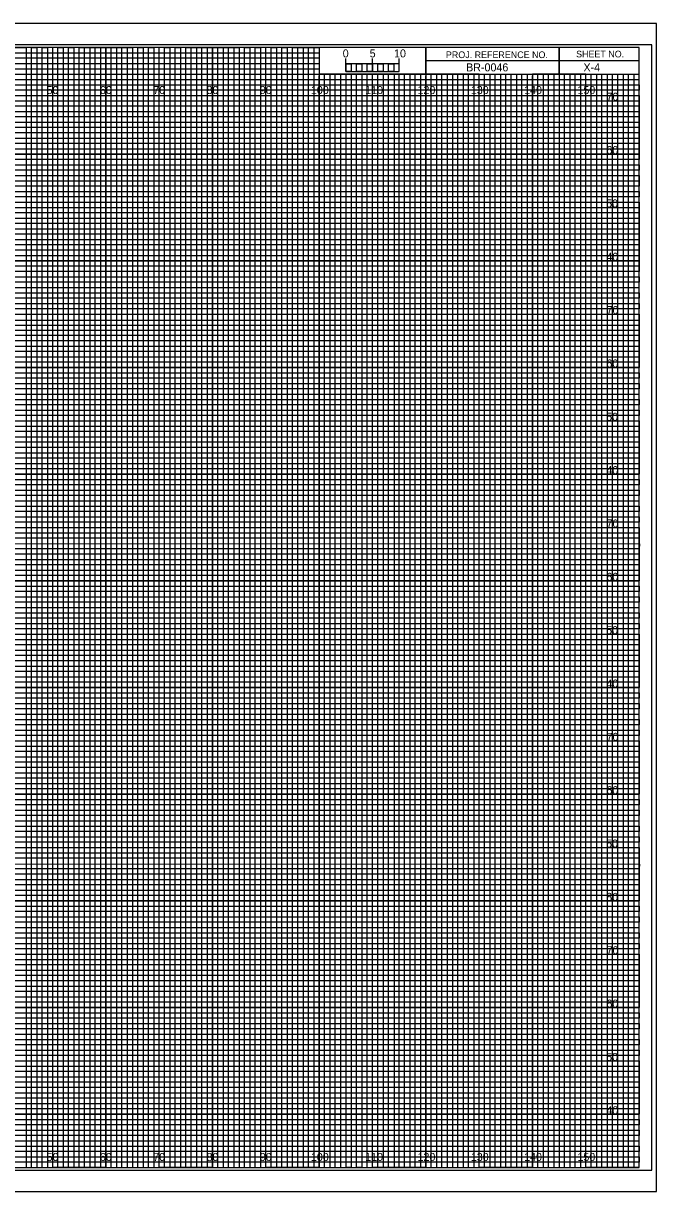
# Model space of a CAD drawing. Extents: x -13 to 323, y 435 to 654.
# Drawn here: x 204.5 to 323.3, y 435.5 to 654.5 of the extents above; entities that cross this region are included whole.
import ezdxf

# ---------------------------------------------------------------- set-up
doc = ezdxf.new("R2010")
doc.units = 0
for name, color, linetype in [('Prop XS Bar Scale Labels', 7, 'Continuous'), ('Prop XS Elevation Labels', 7, 'Continuous'), ('Prop XS Offset Labels', 7, 'Continuous'), ('Prop XS Project Number', 7, 'Continuous'), ('Prop XS Sheet Number', 7, 'Continuous'), ('Sheet Cross Section CELL', 7, 'Continuous'), ('Sheet Cross Section Grid Major CELL', 7, 'Continuous'), ('Sheet Cross Section Grid Middle CELL', 7, 'Continuous'), ('Sheet Cross Section Grid Minor 1 CELL', 7, 'Continuous'), ('Sheet Cross Section Grid Minor 2 CELL', 7, 'Continuous'), ('Sheet Cross Section Scale CELL', 7, 'Continuous'), ('Sheet Cutting Line CELL', 7, 'Continuous'), ('Sheet DOT Grid CELL', 7, 'Continuous'), ('Sheet Plot Border Inside CELL', 7, 'Continuous'), ('Sheet Plot Border Outside CELL', 7, 'Continuous')]:
    doc.layers.add(name, color=color, linetype=linetype)

msp = doc.modelspace()

# ---------------------------------------------------------------- linework, layer by layer
at = {"layer": 'Sheet Cross Section CELL'}
for p, q in [((305, 650), (305, 645)), ((305, 645), (305, 650)), ((280, 647.5), (280, 645)), ((320, 647.49), (280, 647.49)), ((280, 645), (320, 645))]:
    msp.add_line(p, q, dxfattribs=at)
for points in [[(320, 650), (0, 650), (0, 440), (320, 440)], [(280, 650), (260, 650), (260, 645.03), (280, 645.03)], [(320, 650), (280, 650), (280, 645), (320, 645)]]:
    msp.add_lwpolyline(points, close=True, dxfattribs=at)
at = {"layer": 'Sheet Cross Section Grid Major CELL'}
for p, q in [((210, 650), (200, 650)), ((210, 440), (210, 650)), ((230, 650), (220, 650)), ((220, 650), (220, 440)), ((230, 440), (230, 650)), ((250, 650), (240, 650)), ((240, 650), (240, 440)), ((250, 440), (250, 650)), ((260, 650), (260, 440)), ((270, 440), (270, 645)), ((290, 645), (280, 645)), ((280, 645), (280, 440)), ((290, 440), (290, 645)), ((310, 645), (300, 645)), ((300, 645), (300, 440)), ((310, 440), (310, 645)), ((220, 440), (210, 440)), ((240, 440), (230, 440)), ((260, 440), (250, 440)), ((280, 440), (270, 440)), ((300, 440), (290, 440)), ((320, 440), (310, 440)), ((320, 440), (320, 440))]:
    msp.add_line(p, q, dxfattribs=at)
for points in [[(0, 640), (320, 640), (320, 630), (0, 630)], [(0, 620), (320, 620), (320, 610), (0, 610)], [(0, 600), (320, 600), (320, 590), (0, 590)], [(0, 580), (320, 580), (320, 570), (0, 570)], [(0, 560), (320, 560), (320, 550), (0, 550)], [(0, 540), (320, 540), (320, 530), (0, 530)], [(0, 520), (320, 520), (320, 510), (0, 510)], [(0, 500), (320, 500), (320, 490), (0, 490)], [(0, 480), (320, 480), (320, 470), (0, 470)], [(0, 460), (320, 460), (320, 450), (0, 450)]]:
    msp.add_lwpolyline(points, dxfattribs=at)
at = {"layer": 'Sheet Cross Section Grid Middle CELL'}
for points in [[(195, 650), (205, 650), (205, 440), (215, 440), (215, 650), (225, 650), (225, 440), (235, 440), (235, 650), (245, 650), (245, 440), (255, 440), (255, 650), (259.93, 650), (260, 650), (260, 645), (264.99, 645), (264.99, 440), (275, 440), (275, 645), (285, 645), (285, 440), (295, 440), (295, 645), (305, 645), (305, 440), (315, 440), (315, 645)], [(0, 645), (275, 645)], [(0, 625), (320, 625), (320, 635), (0, 635)], [(0, 605), (320, 605), (320, 615), (0, 615)], [(0, 585), (320, 585), (320, 595), (0, 595)], [(0, 565), (320, 565), (320, 575), (0, 575)], [(0, 545), (320, 545), (320, 555), (0, 555)], [(0, 525), (320, 525), (320, 535), (0, 535)], [(0, 505), (320, 505), (320, 515), (0, 515)], [(0, 485), (320, 485), (320, 495), (0, 495)], [(0, 465), (320, 465), (320, 475), (0, 475)], [(0, 445), (320, 445), (320, 455), (0, 455)]]:
    msp.add_lwpolyline(points, dxfattribs=at)
at = {"layer": 'Sheet Cross Section Grid Minor 1 CELL'}
for p, q in [((0, 649), (260, 649)), ((260, 649), (260, 647.98)), ((260, 647.98), (0, 647.98)), ((0, 647), (260, 647)), ((260, 647), (260, 645.89)), ((260, 645.89), (0, 645.89)), ((0, 644), (320, 644))]:
    msp.add_line(p, q, dxfattribs=at)
for points in [[(0, 643), (270, 643), (320, 643), (320, 642), (0, 642)], [(0, 641), (320, 641), (320, 639), (0, 639)], [(0, 638), (320, 638), (320, 637), (0, 636.98)], [(0, 636), (320, 636), (320, 634), (0, 634)], [(0, 633), (320, 633), (320, 632), (0, 632)], [(0, 631), (320, 631), (320, 629), (0, 629)], [(0, 628), (320, 628), (320, 627), (0, 627)], [(0, 626), (320, 626), (320, 624), (0, 624)], [(0, 623), (320, 623), (320, 622), (0, 622)], [(0, 621), (320, 621), (320, 619), (0, 619)], [(0, 618), (320, 618), (320, 617), (0, 617)], [(0, 616), (320, 616), (320, 613.95), (320, 613), (320, 612), (0, 612)], [(0, 614), (320, 614), (320, 613), (0, 613)], [(0, 611), (320, 611), (320, 609), (0, 609.03)], [(0, 609.03), (320, 609), (320, 608), (0, 608)], [(0, 607), (320, 607), (320, 606), (0, 606)], [(0, 604), (320, 604), (320, 603), (0, 603)], [(0, 602), (320, 602), (320, 601), (0, 601)], [(-0.07, 598.89), (320, 598.89), (320, 597.88), (-0.07, 597.88)], [(0, 597), (320, 597), (320, 596), (0, 596)], [(0, 594), (320, 594), (320, 593), (0, 593)], [(0, 592), (320, 592), (320, 591), (0, 591)], [(0, 589), (320, 589), (320, 588), (0, 588)], [(0, 587), (320, 587), (320, 586), (0, 586)], [(0, 584), (320, 584), (320, 583), (0, 583)], [(0, 582), (320, 582), (320, 581), (0, 581)], [(0, 579), (320, 579), (319.99, 577.98), (0, 578)], [(0, 577), (320, 577), (320, 576), (0, 576)], [(0, 574), (320, 574), (320, 573), (0, 573)], [(0, 572), (320, 572), (320, 571), (0, 571)], [(0, 569), (320, 569), (320, 568), (0, 568)], [(0, 567), (320, 567), (320, 566), (0, 566)], [(0, 564), (320, 564), (320, 563), (0, 563)], [(0, 562), (320, 562), (320, 561), (0, 561)], [(0, 559), (320, 559), (320, 558), (0, 558)], [(0, 556.99), (320.07, 556.91), (320, 556), (0, 556)], [(0, 554), (320, 554), (320, 553), (0, 553)], [(0, 552), (320, 552), (320, 551), (0, 551)], [(0, 549), (320, 549), (320, 548), (0, 548)], [(0, 547), (320, 547), (320, 546), (0, 546)], [(0, 544), (320, 544), (320, 543), (0, 543)], [(0, 542), (320, 542), (320, 541), (0, 541)], [(0, 539), (320, 539), (320, 538), (0, 538)], [(0, 537), (320, 537), (320, 536), (0, 536)], [(0, 534), (320, 534), (320, 533), (0, 533)], [(0, 532), (320, 532), (320, 531), (0, 531)], [(0, 529), (320, 529), (320, 528), (0, 528)], [(0, 527), (320, 527), (320, 526), (0, 526)], [(0, 524), (320, 524), (320, 523), (0, 523)], [(0, 522), (320, 522), (320, 521), (0, 521)], [(0, 519), (320, 519), (319.99, 517.98), (0, 518)], [(0, 517), (320, 517), (320, 516), (0, 516)], [(0, 514), (320, 514), (320, 513), (0, 513)], [(0, 512), (320, 512), (320, 511), (0, 511)], [(0, 509), (320, 509), (320, 508), (0, 508)], [(0, 507), (320, 507), (320, 506), (0, 506)], [(0, 504), (320, 504), (320, 503), (0, 503)], [(0, 502), (320, 502), (320, 501), (0, 501)], [(0, 499), (320, 499), (320, 498), (0, 498)], [(0, 496.99), (320.07, 496.91), (320, 496), (0, 496)], [(0, 494), (320, 494), (320, 493), (0, 493)], [(0, 492), (320, 492), (320, 491), (0, 491)], [(0, 489), (320, 489), (320, 488), (0, 488)], [(0, 487), (320, 487), (320, 486), (0, 486)], [(0, 484), (320, 484), (320, 483), (0, 483)], [(0, 482), (320, 482), (320, 481), (0, 481)], [(0, 479), (320, 479), (320, 478), (0, 478)], [(0, 477), (320, 477), (320, 476), (0, 476)], [(0, 474), (320, 474), (320, 473), (0, 473)], [(0, 472), (320, 472), (320, 471), (0, 471)], [(0, 469), (320, 469), (320, 468), (0, 468)], [(0, 467), (320, 467), (320, 466), (0, 466)], [(0, 464), (320, 464), (320, 463), (0, 463)], [(0, 462), (320, 462), (320, 461), (0, 461)], [(0, 459), (320, 459), (320, 458), (0, 458)], [(0, 457), (320, 457), (320, 456), (0, 456)], [(0, 454), (320, 454), (320, 453), (0, 453)], [(0, 452), (320, 452), (320, 451), (0, 451)], [(0, 449), (320, 449), (320, 448), (0, 448)], [(0, 447), (320, 447), (320, 446), (0, 446)], [(0, 444), (320, 444), (320, 443), (0, 443)], [(0, 442), (320, 442), (320, 441), (0, 441)]]:
    msp.add_lwpolyline(points, dxfattribs=at)
at = {"layer": 'Sheet Cross Section Grid Minor 2 CELL'}
for p, q in [((267, 645), (266.01, 645)), ((266.01, 645), (266.01, 440)), ((267, 440), (267, 645)), ((269, 645), (268, 645)), ((268, 645), (268, 440)), ((269, 440), (269, 645)), ((266.01, 440), (265, 440)), ((268, 440), (267, 440))]:
    msp.add_line(p, q, dxfattribs=at)
for points in [[(205, 440), (206, 440), (206, 650), (207, 650), (207, 440)], [(207, 440), (208, 440), (208, 650), (209, 650), (209, 440)], [(210, 440), (211, 440), (211, 650), (212, 650), (212, 440)], [(212, 440), (213, 440), (213, 650), (214, 650), (214, 440)], [(215, 440), (216, 440), (216, 650), (217, 650), (217, 440)], [(217, 440), (218, 440), (218, 650), (219, 650), (219, 440)], [(220, 440), (221, 440), (221, 650), (222, 650), (222, 440)], [(222, 440), (223, 440), (223, 650), (224, 650), (224, 440)], [(225, 440), (226, 440), (226, 650), (227, 650), (227, 440)], [(227, 440), (228, 440), (228, 650), (229, 650), (229, 440)], [(230, 440), (231, 440), (231, 650), (232, 650), (232, 440)], [(232, 440), (233, 440), (233, 650), (234, 650), (234, 440)], [(235, 440), (236, 440), (236, 650), (237, 650), (237, 440)], [(237, 440), (238, 440), (238, 650), (239, 650), (239, 440)], [(240, 440), (241, 440), (241, 650), (242, 650), (242, 440)], [(242, 440), (243, 440), (243, 650), (244, 650), (244, 440)], [(245, 440), (246, 440), (246, 650), (247, 650), (247, 440)], [(247, 440), (248, 440), (248, 650), (249, 650), (249, 440)], [(250, 440), (251, 440), (251, 650), (252, 650), (252, 440)], [(252, 440), (253, 440), (253, 650), (254, 650), (254, 440)], [(255, 440), (256, 440), (256, 650), (257, 650), (257, 440)], [(257, 440), (258, 440), (258, 650), (259, 650), (259, 440)], [(260, 440), (261, 440), (261, 645), (262.02, 645), (262.02, 440)], [(262, 440), (263, 440), (263, 645), (263.99, 645), (263.99, 440)], [(270, 440), (270.98, 440), (270.98, 645), (272, 645), (272, 440)], [(272, 440), (273, 440), (273, 645), (274.05, 645), (274.05, 440)], [(275, 440), (276, 440), (276, 645), (277, 645), (277, 440)], [(277, 440), (278, 440), (278, 645), (279, 645), (279, 440)], [(280, 440), (281, 440), (281, 645), (282, 645), (282, 440)], [(282, 440), (283, 440), (283, 645), (284, 645), (284, 440)], [(285, 440), (286, 440), (286, 645), (287, 645), (287, 440)], [(287, 440), (288, 440), (288, 645), (289, 645), (289, 440)], [(290, 440), (291, 440), (291, 645), (292, 645), (292, 440)], [(292, 440), (293, 440), (293, 645), (294, 645), (294, 440)], [(295, 440), (296, 440), (296, 645), (297, 645), (297, 440)], [(297, 440), (298, 440), (298, 645), (299, 645), (299, 440)], [(300, 440), (301, 440), (301, 645), (302, 645), (302, 440)], [(302, 440), (303, 440), (303, 645), (304, 645), (304, 440)], [(305, 440), (306, 440), (306, 645), (307, 645), (307, 440)], [(307, 440), (308, 440), (308, 645), (309, 645), (309, 440)], [(310, 440), (311, 440), (311, 645), (312, 645), (312, 440)], [(312, 440), (313, 440), (313, 645), (314, 645), (314, 440)], [(315, 440), (316, 440), (316, 645), (317, 645), (317, 440)], [(317, 440), (318, 440), (318, 645), (319, 645), (319, 440)]]:
    msp.add_lwpolyline(points, dxfattribs=at)
at = {"layer": 'Sheet Cross Section Scale CELL'}
for p, q in [((265, 645.49), (265, 647.9)), ((265, 646.9), (265, 647.9)), ((270, 645.49), (270, 647.9)), ((275, 645.49), (275, 647.9)), ((275, 646.9), (275, 647.9))]:
    msp.add_line(p, q, dxfattribs=at)
for points in [[(275, 646.9), (265, 646.9), (265, 645.49), (275, 645.49)], [(265, 646.9), (266, 646.9), (266, 645.49), (265, 645.49)], [(267, 646.9), (268, 646.9), (268, 645.49), (267, 645.49)], [(269, 646.9), (270, 646.9), (270, 645.49), (269, 645.49)], [(271, 646.9), (272, 646.9), (272, 645.49), (271, 645.49)], [(273, 646.9), (274, 646.9), (274, 645.49), (273, 645.49)]]:
    msp.add_lwpolyline(points, close=True, dxfattribs=at)
at = {"layer": 'Sheet Cutting Line CELL'}
for p, q in [((323.3, 654.5), (-13.4, 654.5)), ((-13.4, 435.5), (323.3, 435.5))]:
    msp.add_line(p, q, dxfattribs=at)
at = {"layer": 'Sheet DOT Grid CELL'}
for p, q in [((210, 440), (210, 650)), ((220, 440), (220, 650)), ((230, 440), (230, 650)), ((240, 440), (240, 650)), ((250, 440), (250, 650)), ((260, 440), (260, 644.69)), ((270, 440), (270, 644.69)), ((280, 440), (280, 644.69)), ((290, 440), (290, 644.69)), ((300, 440), (300, 644.69)), ((310, 440), (310, 644.69)), ((0, 640), (320, 640)), ((0, 630), (320, 630)), ((0, 620), (320, 620)), ((0, 610), (320, 610)), ((0, 600), (320, 600)), ((0, 590), (320, 590)), ((0, 580), (320, 580)), ((0, 570), (320, 570)), ((0, 560), (320, 560)), ((0, 550), (320, 550)), ((0, 540), (320, 540)), ((0, 530), (320, 530)), ((0, 520), (320, 520)), ((0, 510), (320, 510)), ((0, 500), (320, 500)), ((0, 490), (320, 490)), ((0, 480), (320, 480)), ((0, 470), (320, 470)), ((0, 460), (320, 460)), ((0, 450), (320, 450))]:
    msp.add_line(p, q, dxfattribs=at)
at = {"layer": 'Sheet Plot Border Inside CELL'}
msp.add_lwpolyline([(-10.8, 439.5), (322.4, 439.5), (322.4, 650.5), (-10.8, 650.5)], close=True, dxfattribs=at)
at = {"layer": 'Sheet Plot Border Outside CELL'}
msp.add_lwpolyline([(-13.4, 435.5), (323.3, 435.5), (323.3, 654.5), (-13.4, 654.5)], close=True, dxfattribs=at)

# ---------------------------------------------------------------- texts
at = {"layer": 'Prop XS Bar Scale Labels'}
for s, p in [('5', (269.47, 648.12)), ('10', (274.04, 648.12))]:
    msp.add_text(s, height=1.5, dxfattribs=at).set_placement(p)
at = {"layer": 'Prop XS Elevation Labels'}
for s, p in [('70', (313.9, 640)), ('60', (313.87, 630)), ('50', (313.82, 620)), ('40', (313.87, 610)), ('70', (313.9, 600)), ('60', (313.87, 590)), ('50', (313.82, 580)), ('40', (313.87, 570)), ('70', (313.9, 560)), ('60', (313.87, 550)), ('50', (313.82, 540)), ('40', (313.87, 530)), ('70', (313.9, 520)), ('60', (313.87, 510)), ('50', (313.82, 500)), ('80', (313.84, 490)), ('70', (313.9, 480)), ('60', (313.87, 470)), ('50', (313.82, 460)), ('40', (313.87, 450))]:
    msp.add_text(s, height=1.5, dxfattribs=at).set_placement(p)
at = {"layer": 'Prop XS Offset Labels'}
for s, p in [('50', (208.86, 641.25)), ('60', (218.86, 641.25)), ('70', (228.86, 641.25)), ('80', (238.86, 641.25)), ('90', (248.86, 641.25)), ('100', (258.44, 641.25)), ('110', (268.62, 641.25)), ('120', (278.44, 641.25)), ('130', (288.44, 641.25)), ('140', (298.44, 641.25)), ('150', (308.44, 641.25)), ('50', (208.86, 441.25)), ('60', (218.86, 441.25)), ('70', (228.86, 441.25)), ('80', (238.86, 441.25)), ('90', (248.86, 441.25)), ('100', (258.44, 441.25)), ('110', (268.62, 441.25)), ('120', (278.44, 441.25)), ('130', (288.44, 441.25)), ('140', (298.44, 441.25)), ('150', (308.44, 441.25))]:
    msp.add_text(s, height=1.5, dxfattribs=at).set_placement(p)
at = {"layer": 'Prop XS Project Number'}
msp.add_text('BR-0046', height=1.5, dxfattribs=at).set_placement((287.56, 645.5))
at = {"layer": 'Prop XS Sheet Number'}
msp.add_text('X-4', height=1.5, dxfattribs=at).set_placement((309.57, 645.5))
at = {"layer": 'Sheet Cross Section CELL'}
for s, p in [('PROJ. REFERENCE NO.', (283.77, 647.99)), ('SHEET NO.', (308.19, 648.12))]:
    msp.add_text(s, height=1.25, dxfattribs=at).set_placement(p)
at = {"layer": 'Sheet Cross Section Scale CELL'}
msp.add_text('0', height=1.5, dxfattribs=at).set_placement((264.41, 648.12))

doc.saveas('drawing.dxf')
